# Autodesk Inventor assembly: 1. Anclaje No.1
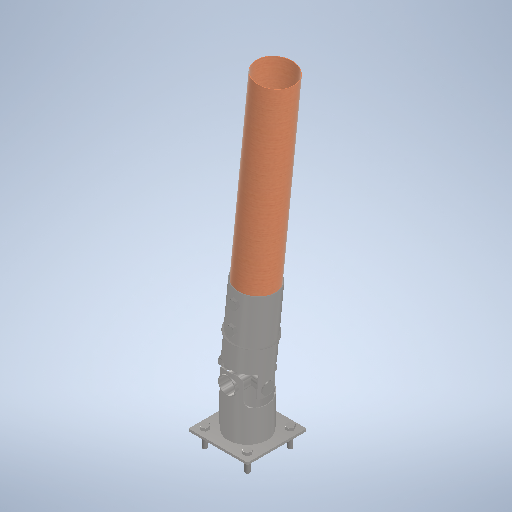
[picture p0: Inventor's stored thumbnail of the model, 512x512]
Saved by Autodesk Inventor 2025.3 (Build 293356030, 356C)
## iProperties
Created: 2025-10
Part Number: 1. Anclaje No.1
Document SubType Name: Assembly
Designer: Asus
Author: Asus
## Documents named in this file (10)
- C:\Users\User\OneDrive - Institucion Universitaria Colegio Mayor de Antioquia\Escritorio\PROTECTO INV\Anclajes Profesor\1. Anclaje\1. Anclaje No.1.iam
- C:\Users\User\OneDrive - Institucion Universitaria Colegio Mayor de Antioquia\Escritorio\PROTECTO INV\Anclajes Profesor\1. Anclaje\Conector Base (Ensamble).iam
- C:\Users\User\OneDrive - Institucion Universitaria Colegio Mayor de Antioquia\Escritorio\PROTECTO INV\Anclajes Profesor\1. Anclaje\Tubo Interior 1.ipt
- C:\Users\User\OneDrive - Institucion Universitaria Colegio Mayor de Antioquia\Escritorio\PROTECTO INV\Anclajes Profesor\1. Anclaje\Tubo Exterior 1.ipt
- C:\Users\User\OneDrive - Institucion Universitaria Colegio Mayor de Antioquia\Escritorio\PROTECTO INV\Anclajes Profesor\1. Anclaje\Conector a Guadua (Ensamble).iam
- C:\Users\User\OneDrive - Institucion Universitaria Colegio Mayor de Antioquia\Escritorio\PROTECTO INV\Anclajes Profesor\1. Anclaje\Pin.ipt
- C:\Users\User\OneDrive - Institucion Universitaria Colegio Mayor de Antioquia\Escritorio\PROTECTO INV\Anclajes Profesor\1. Anclaje\Tapa Pin.ipt
- C:\Users\User\OneDrive - Institucion Universitaria Colegio Mayor de Antioquia\Escritorio\PROTECTO INV\Anclajes Profesor\1. Anclaje\Guadua.ipt
- C:\Users\User\OneDrive - Institucion Universitaria Colegio Mayor de Antioquia\Documentos\Inventor\Content Center Files\R2025\es-ES\AS 1110\AS 1110 - M24 x 80.ipt
- C:\Users\User\OneDrive - Institucion Universitaria Colegio Mayor de Antioquia\Documentos\Inventor\Content Center Files\R2025\es-ES\AS 1110\AS 1110 - M20 x 70.ipt
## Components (15 placed, 9 different names)
1. Conector Base (Ensamble):1 [sub-assembly] — Nivelación:1, Nivelación:2, Nivelación:3, Coincidencia:1, Nivelación:4, Nivelación:5, Coincidencia:15, Coincidencia:24, Coincidencia:26, Coincidencia:28, Coincidencia:30
2. Tubo Interior 1:1 — Coincidencia:1, Nivelación:4, Coincidencia:16, Coincidencia:17, Nivelación:6
3. Tubo Exterior 1:1 — Nivelación:5, Coincidencia:13, Coincidencia:15
4. Conector a Guadua (Ensamble):1 [sub-assembly]
5. Tapa Pin:1 — Coincidencia:18, Coincidencia:19
6. Guadua:1 — Coincidencia:21, Coincidencia:22
7. Pin:1 — Coincidencia:17, Tangente:1, Coincidencia:18, Coincidencia:19
8. AS 1110 - Métrico M20 x 70:1 — Coincidencia:24
9. AS 1110 - Métrico M20 x 70:2 — Coincidencia:26
10. AS 1110 - Métrico M20 x 70:3 — Coincidencia:28
11. AS 1110 - Métrico M20 x 70:4 — Coincidencia:30
12. AS 1110 - Métrico M24 x 80:1 — Rígido:4
13. AS 1110 - Métrico M24 x 80:2 — Rígido:3
14. AS 1110 - Métrico M24 x 80:3 — Coincidencia:34, Rígido:2
15. AS 1110 - Métrico M24 x 80:4 — Coincidencia:33, Rígido:1
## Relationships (26: Mate 15, Flush 6, WeldJoint 4, Tangent 1)
- Nivelación:1 [Flush]: Conector Base (Ensamble):1
- Nivelación:2 [Flush]: Conector Base (Ensamble):1
- Nivelación:3 [Flush]: Conector Base (Ensamble):1
- Coincidencia:1 [Mate]: Conector Base (Ensamble):1 ↔ Tubo Interior 1:1
- Nivelación:4 [Flush]: Conector Base (Ensamble):1 ↔ Tubo Interior 1:1
- Nivelación:5 [Flush]: Conector Base (Ensamble):1 ↔ Tubo Exterior 1:1
- Coincidencia:13 [Mate]: Tubo Exterior 1:1
- Coincidencia:15 [Mate]: Conector Base (Ensamble):1 ↔ Tubo Exterior 1:1
- Coincidencia:16 [Mate]: Tubo Interior 1:1
- Coincidencia:17 [Mate]: Tubo Interior 1:1 ↔ Pin:1
- Tangente:1: Pin:1
- Coincidencia:18 [Mate]: Tapa Pin:1 ↔ Pin:1
- Coincidencia:19 [Mate]: Tapa Pin:1 ↔ Pin:1
- Nivelación:6 [Flush]: Tubo Interior 1:1
- Coincidencia:21 [Mate]: Guadua:1
- Coincidencia:22 [Mate]: Guadua:1
- Coincidencia:24 [Mate]: Conector Base (Ensamble):1 ↔ AS 1110 - Métrico M20 x 70:1
- Coincidencia:26 [Mate]: Conector Base (Ensamble):1 ↔ AS 1110 - Métrico M20 x 70:2
- Coincidencia:28 [Mate]: Conector Base (Ensamble):1 ↔ AS 1110 - Métrico M20 x 70:3
- Coincidencia:30 [Mate]: Conector Base (Ensamble):1 ↔ AS 1110 - Métrico M20 x 70:4
- Coincidencia:33 [Mate]: AS 1110 - Métrico M24 x 80:4
- Coincidencia:34 [Mate]: AS 1110 - Métrico M24 x 80:3
- Rígido:1 [WeldJoint]: AS 1110 - Métrico M24 x 80:4
- Rígido:2 [WeldJoint]: AS 1110 - Métrico M24 x 80:3
- Rígido:3 [WeldJoint]: AS 1110 - Métrico M24 x 80:2
- Rígido:4 [WeldJoint]: AS 1110 - Métrico M24 x 80:1
